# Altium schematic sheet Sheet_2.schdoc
size 319 x 214 mm
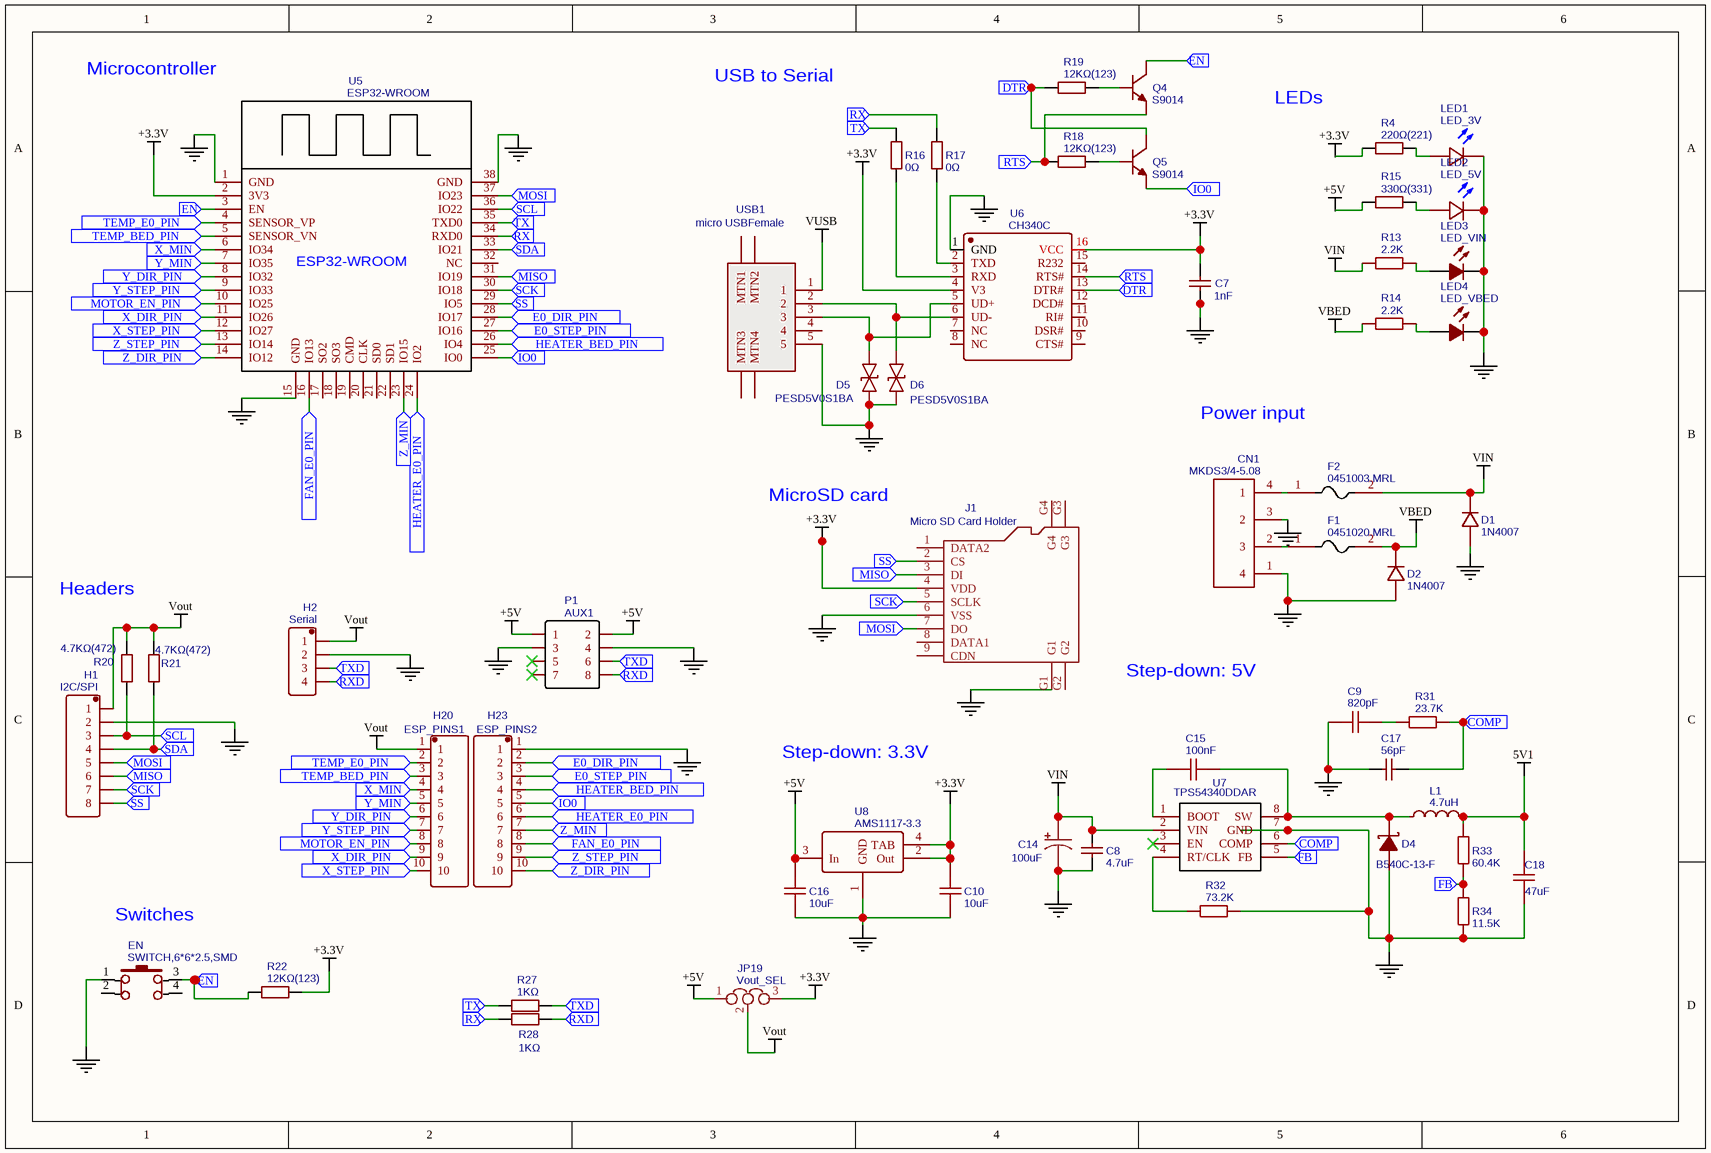
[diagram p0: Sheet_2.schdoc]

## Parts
C7  1nF  [0805]
C8  4.7uF  [1206]
C9  820pF  [0805]
C10  10uF  [0805]
C14  100uF  [CAP-T-8*10]
C15  100nF  [0805]
C16  10uF  [0805]
C17  56pF  [0805]
C18  47uF  [1206]
CN1  MKDS3/4-5.08  [MKDS3/4-5.08]
D1  1N4007  [SOD-123F]
D2  1N4007  [SOD-123F]
D4  B540C-13-F  [SMC(DO-214AB)]
D5  PESD5V0S1BA  [SOD-323]
D6  PESD5V0S1BA  [SOD-323]
EN  SWITCH,6*6*2.5,SMD  [KEY-6.0*6.0]
F1  0451020.MRL  [SMF_045X]
F2  0451003.MRL  [SMF_045X]
H1  I2C/SPI  [210S-1X8P]
H2  Serial  [DIP-1X4P-2.54MM-M]
H20  ESP_PINS1  [DIP-1X10P-2.54MM-M]
H23  ESP_PINS2  [DIP-1X10P-2.54MM-M]
J1  Micro SD Card Holder  [MICRO-SD9+4P-SMD-16.1X14.5X1.85MM]
JP19  Vout_SEL  [HDR-3X1/2.54]
L1  4.7uH  [0530]
LED1  LED_3V  [LED-0805]
LED2  LED_5V  [LED-0805]
LED3  LED_VIN  [LED-0805]
LED4  LED_VBED  [LED-0805]
P1  AUX1  [HDR-IDC-2.54-2X4P]
Q4  S9014  [SOT-23(SOT-23-3)]
Q5  S9014  [SOT-23(SOT-23-3)]
R4  220Ω(221)  [0805]
R13  2.2K  [0805]
R14  2.2K  [0805]
R15  330Ω(331)  [0805]
R16  0Ω  [0805]
R17  0Ω  [0805]
R18  12KΩ(123)  [0805]
R19  12KΩ(123)  [0805]
R20  4.7KΩ(472)  [0805]
R21  4.7KΩ(472)  [0805]
R22  12KΩ(123)  [0805]
R27  1KΩ  [0805]
R28  1KΩ  [0805]
R31  23.7K  [0805]
R32  73.2K  [0805]
R33  60.4K  [0805]
R34  11.5K  [R0805]
U5  ESP32-WROOM  [ESP32_WROOM_FOOTPRINT]
U6  CH340C  [SOP-16_150MIL]
U7  TPS54340DDAR  [SOIC-8_150MIL-EP]
U8  AMS1117-3.3  [SOT-223]
USB1  micro USBFemale  [MICRO-USB-1]

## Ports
COMP, DTR, E0_DIR_PIN, E0_STEP_PIN, EN, FAN_E0_PIN, FB, HEATER_BED_PIN, HEATER_E0_PIN, IO0, MISO, MOSI, MOTOR_EN_PIN, RTS, RX, RXD, SCK, SCL, SDA, SS, TEMP_BED_PIN, TEMP_E0_PIN, TX, TXD, X_DIR_PIN, X_MIN, X_STEP_PIN, Y_DIR_PIN, Y_MIN, Y_STEP_PIN, Z_DIR_PIN, Z_MIN, Z_STEP_PIN

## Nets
5V1: L1.2
+3.3V: C7.1 J1.4(VDD) JP19.3 R4.1 R22.2 U5.2(3V3) U6.4(V3) U6.16(VCC) U8.2(Out) U8.4(TAB)
+5V: JP19.1 P1.1 P1.2 R15.1 U8.3(In)
GND: C7.2 C8.2 C14.2 C17.1 CN1.1(4) CN1.3(2) D1.1(+) D2.1(+) D4.1(A) D5.2(A) D6.2(A) EN.1 H1.2 H2.2 H23.1 J1.6(VSS) J1.G1 LED1.2(-) LED2.2(-) LED3.2(C) LED4.2(C) P1.3 P1.4 U5.1(GND) U5.15(GND) U5.38(GND) U6.1(GND) U7.7(GND) U8.1(GND) USB1.5
VBED: D2.2(-) F1.2
VIN: C8.1 C14.1 D1.2(-) F2.2 U7.2(VIN)
Vout: H1.1 H2.1 H20.1 JP19.2 R20.2 R21.2
VUSB: USB1.1
COMP: C17.2 U7.6(COMP) ; port COMP
DTR: Q5.3(C) R19.1 U6.13(DTR#) ; port DTR
E0_DIR_PIN: H23.2 U5.28(IO17) ; port E0_DIR_PIN
E0_STEP_PIN: H23.3 U5.27(IO16) ; port E0_STEP_PIN
EN: EN.3 Q4.3(C) R22.1 U5.3(EN) ; port EN
FAN_E0_PIN: H23.8 U5.16(IO13) ; port FAN_E0_PIN
FB: U7.5(FB) ; port FB
HEATER_BED_PIN: H23.4 U5.26(IO4) ; port HEATER_BED_PIN
HEATER_E0_PIN: H23.6 U5.24(IO2) ; port HEATER_E0_PIN
IO0: H23.5 Q5.2(E) U5.25(IO0) ; port IO0
MISO: H1.6 J1.3(DI) U5.31(IO19) ; port MISO
MOSI: H1.5 J1.7(DO) U5.37(IO23) ; port MOSI
MOTOR_EN_PIN: H20.8 U5.10(IO25) ; port MOTOR_EN_PIN
RTS: Q4.2(E) R18.1 U6.14(RTS#) ; port RTS
RX: R17.2 R28.1 U5.34(RXD0) ; port RX
RXD: H2.4 P1.8 R28.2 ; port RXD
SCK: H1.7 J1.5(SCLK) U5.30(IO18) ; port SCK
SCL: H1.3 R20.1 U5.36(IO22) ; port SCL
SDA: H1.4 R21.1 U5.33(IO21) ; port SDA
SS: H1.8 J1.2(CS) U5.29(IO5) ; port SS
TEMP_BED_PIN: H20.3 U5.5(SENSOR_VN) ; port TEMP_BED_PIN
TEMP_E0_PIN: H20.2 U5.4(SENSOR_VP) ; port TEMP_E0_PIN
TX: R16.2 R27.1 U5.35(TXD0) ; port TX
TXD: H2.3 P1.6 R27.2 ; port TXD
X_DIR_PIN: H20.9 U5.11(IO26) ; port X_DIR_PIN
X_MIN: H20.4 U5.6(IO34) ; port X_MIN
X_STEP_PIN: H20.10 U5.12(IO27) ; port X_STEP_PIN
Y_DIR_PIN: H20.6 U5.8(IO32) ; port Y_DIR_PIN
Y_MIN: H20.5 U5.7(IO35) ; port Y_MIN
Y_STEP_PIN: H20.7 U5.9(IO33) ; port Y_STEP_PIN
Z_DIR_PIN: H23.10 U5.14(IO12) ; port Z_DIR_PIN
Z_MIN: H23.7 U5.23(IO15) ; port Z_MIN
Z_STEP_PIN: H23.9 U5.13(IO14) ; port Z_STEP_PIN
NetCN1_2: CN1.2(3) F1.1
NetCN1_4: CN1.4(1) F2.1
NetD4_2: D4.2(K) L1.1 U7.8(SW)
NetD5_1: D5.1(K) U6.5(UD+) USB1.3
NetD6_1: D6.1(K) U6.6(UD-) USB1.2
NetLED1_1: LED1.1(+) R4.2
NetLED2_1: LED2.1(+) R15.2
NetQ4_1: Q4.1(B) R19.2
NetQ5_1: Q5.1(B) R18.2
NetR16_1: R16.1 U6.3(RXD)
NetR17_1: R17.1 U6.2(TXD)

Not connected (* = marked no-connect by the designer): C9 1 2; C10 1 2; C15 1 2; C16 1 2; C18 1 2; EN 2 4; J1 1(DATA2) 8(DATA1) 9(CDN) G2 G3 G4; LED3 1(A); LED4 1(A); P1 5* 7*; R13 1 2; R14 1 2; R31 1 2; R32 1 2; R33 1 2; R34 1 2; U5 17(SO2) 18(SO3) 19(CMD) 20(CLK) 21(SD0) 22(SD1) 32(NC); U6 7(NC) 8(NC) 9(CTS#) 10(DSR#) 11(RI#) 12(DCD#) 15(R232); U7 1(BOOT) 3(EN)* 4(RT/CLK); USB1 0(MTN4) 4

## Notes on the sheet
- Microcontroller
- USB to Serial
- LEDs
- Power input
- MicroSD card
- Headers
- Step-down: 5V
- Step-down: 3.3V
- (near EN) Switches

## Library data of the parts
C7 = 1nF: BOM_Manufacturer: YAGEO; BOM_Manufacturer Part: CC0805KRX7RABB102; nameAlias: Capacitance
C8 = 4.7uF: BOM_Manufacturer: MuRata; BOM_Manufacturer Part: GRM31CR71H475KA12L; nameAlias: Capacitance
C9 = 820pF: BOM_Manufacturer: Murata Electronics; BOM_Manufacturer Part: GRM2165C1H821JA01D; nameAlias: Capacitance; Contributor: LCSC
C10 C16 = 10uF: BOM_Manufacturer: FH; BOM_Manufacturer Part: 0805B106K250NT; nameAlias: Capacitance
C14 = 100uF: BOM_Manufacturer: Lelon; BOM_Manufacturer Part: VZH101M1HTR-0810; nameAlias: Capacitance; Contributor: LCSC
C15 = 100nF: BOM_Manufacturer: MuRata; BOM_Manufacturer Part: GRM21BR71E104KA01L; nameAlias: Capacitance
C17 = 56pF: BOM_Manufacturer: FH; BOM_Manufacturer Part: 0805CG560J500NT; nameAlias: Capacitance
C18 = 47uF: BOM_Manufacturer: FH; BOM_Manufacturer Part: 1206X476M160NT; nameAlias: Capacitance; Contributor: LCSC
CN1 = MKDS3/4-5.08: BOM_Manufacturer: Phoenix Contact
D1 D2 = 1N4007: BOM_Manufacturer: Hottech; Contributor: LCSC
D4 = B540C-13-F: BOM_Manufacturer: DIODES
D5 D6 = PESD5V0S1BA: BOM_Manufacturer: Nexperia; BOM_Manufacturer Part: PESD5V0S1BA,115
EN = SWITCH,6*6*2.5,SMD: BOM_Manufacturer: BBJ; BOM_Manufacturer Part: Switch,6*6*2.5Plastic head,260G, 0.25mm,SMD; Contributor: LCSC
F1 = 0451020.MRL: BOM_Manufacturer: Littelfuse
F2 = 0451003.MRL: BOM_Manufacturer: Littelfuse
H1 = I2C/SPI: BOM_Manufacturer: Ckmtw; BOM_Manufacturer Part: 210S-1*8P L=11.6MMGold-plated black; Contributor: LCSC
H2 = Serial: BOM_Manufacturer: Ckmtw; BOM_Manufacturer Part: 210S-1*4P L=11.6MMGold-plated black; Contributor: LCSC
H20 = ESP_PINS1: BOM_Manufacturer: Ckmtw; BOM_Manufacturer Part: 210S-1*10P L=11.6MMGold-plated black; Contributor: LCSC
H23 = ESP_PINS2: BOM_Manufacturer: Ckmtw; BOM_Manufacturer Part: 210S-1*10P L=11.6MMGold-plated black; Contributor: LCSC
J1 = Micro SD Card Holder: BOM_Manufacturer Part: LCSC; description: Micro SD Card Holder;
JP19 = Vout_SEL: Contributor: KiCad
L1 = 4.7uH: BOM_Manufacturer: ShunXiang Connaught Elec; BOM_Manufacturer Part: SMMS0530-4R7M; nameAlias: Inductance; Contributor: LCSC
LED1 = LED_3V: BOM_Manufacturer: Everlight Elec; BOM_Manufacturer Part: 17-21/BHC-XL2M2TY/3T
LED2 = LED_5V: BOM_Manufacturer: Everlight Elec; BOM_Manufacturer Part: 17-21/BHC-XL2M2TY/3T
LED3 = LED_VIN: BOM_Manufacturer: EVERLIGHT; BOM_Manufacturer Part: 17-21/GHC-YR1S2/3T
LED4 = LED_VBED: BOM_Manufacturer: EVERLIGHT; BOM_Manufacturer Part: 17-21/GHC-YR1S2/3T
P1 = AUX1: BOM_Manufacturer: BOOMELE; BOM_Manufacturer Part: IDC Box 2X4 2.54MM
Q4 Q5 = S9014: BOM_Manufacturer: Hottech; Contributor: LCSC
R4 = 220Ω(221): BOM_Manufacturer: YAGEO; BOM_Manufacturer Part: RC0805JR-07220RL; nameAlias: Value
R13 R14 = 2.2K: BOM_Manufacturer: YAGEO; BOM_Manufacturer Part: RC0805JR-072K2L; nameAlias: Resistance (Ohms); Contributor: LCSC
R15 = 330Ω(331): BOM_Manufacturer: YAGEO; BOM_Manufacturer Part: RC0805JR-07330RL; nameAlias: Value
R16 R17 = 0Ω: BOM_Manufacturer: YAGEO; BOM_Manufacturer Part: RC0805JR-070RL; nameAlias: Value
R18 R19 R22 = 12KΩ(123): BOM_Manufacturer: YAGEO; BOM_Manufacturer Part: RC0805JR-0712KL; nameAlias: Value
R20 R21 = 4.7KΩ(472): BOM_Manufacturer: YAGEO; BOM_Manufacturer Part: RC0805JR-074K7L; nameAlias: Value
R27 R28 = 1KΩ: BOM_Manufacturer: YAGEO; BOM_Manufacturer Part: RC0805JR-071KL; nameAlias: Value
R31 = 23.7K: BOM_Manufacturer: YAGEO; BOM_Manufacturer Part: AC0805FR-0723K7L; nameAlias: Resistance (Ohms); Contributor: LCSC
R32 = 73.2K: BOM_Manufacturer: YAGEO; BOM_Manufacturer Part: AC0805FR-0773K2L; nameAlias: Resistance (Ohms); Contributor: LCSC
R33 = 60.4K: BOM_Manufacturer: YAGEO; BOM_Manufacturer Part: AC0805FR-0760K4L; nameAlias: Resistance (Ohms); Contributor: LCSC
R34 = 11.5K: BOM_Manufacturer: YAGEO; BOM_Manufacturer Part: AC0805FR-0711K5L; nameAlias: Resistance (Ohms); Contributor: LCSC
U5 = ESP32-WROOM: Contributor: cunt123
U6 = CH340C: BOM_Manufacturer: WCH
U7 = TPS54340DDAR: BOM_Manufacturer: TI
U8 = AMS1117-3.3: BOM_Manufacturer: AMS; sourceId: dwIGgezVh
USB1 = micro USBFemale: BOM_Manufacturer: ValuePro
